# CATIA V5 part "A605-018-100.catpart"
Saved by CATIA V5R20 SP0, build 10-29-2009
Part number: A605-018-100
Source: Unknown
Property "A": "0.000"
Property "ARTICLENO": "A605-018-100"
Property "BOMINFO": "A605-018-100"
Property "CODE": "A605-018-100"
Property "D": "6.500"
Property "FORM": "A"
Property "L": "100.000"
Property "L1": "70.000"
Property "LINA": "A605-018-100"
Property "NB": "A605-018-100"
Property "NBSYN": "$CODE."
Property "NN": "A605"
Property "NT": "Wear Plates, self-lubricating"
Property "SCREW": "2*M6X10"
Property "SUPPLIER": "CF"
Property "W": "18.000"
Bounding box of the stored display mesh (mm): x -18 to 0, y 0 to 5, z -100 to 0
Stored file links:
  C:\Users\Utente\Desktop\3D files A605\A605-018-100.catpart
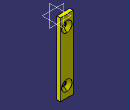
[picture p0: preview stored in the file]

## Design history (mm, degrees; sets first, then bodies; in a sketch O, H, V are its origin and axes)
Body1 "Geometry.1" (main body)
  Solid1 "A605-018-100.catpart": solid without history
